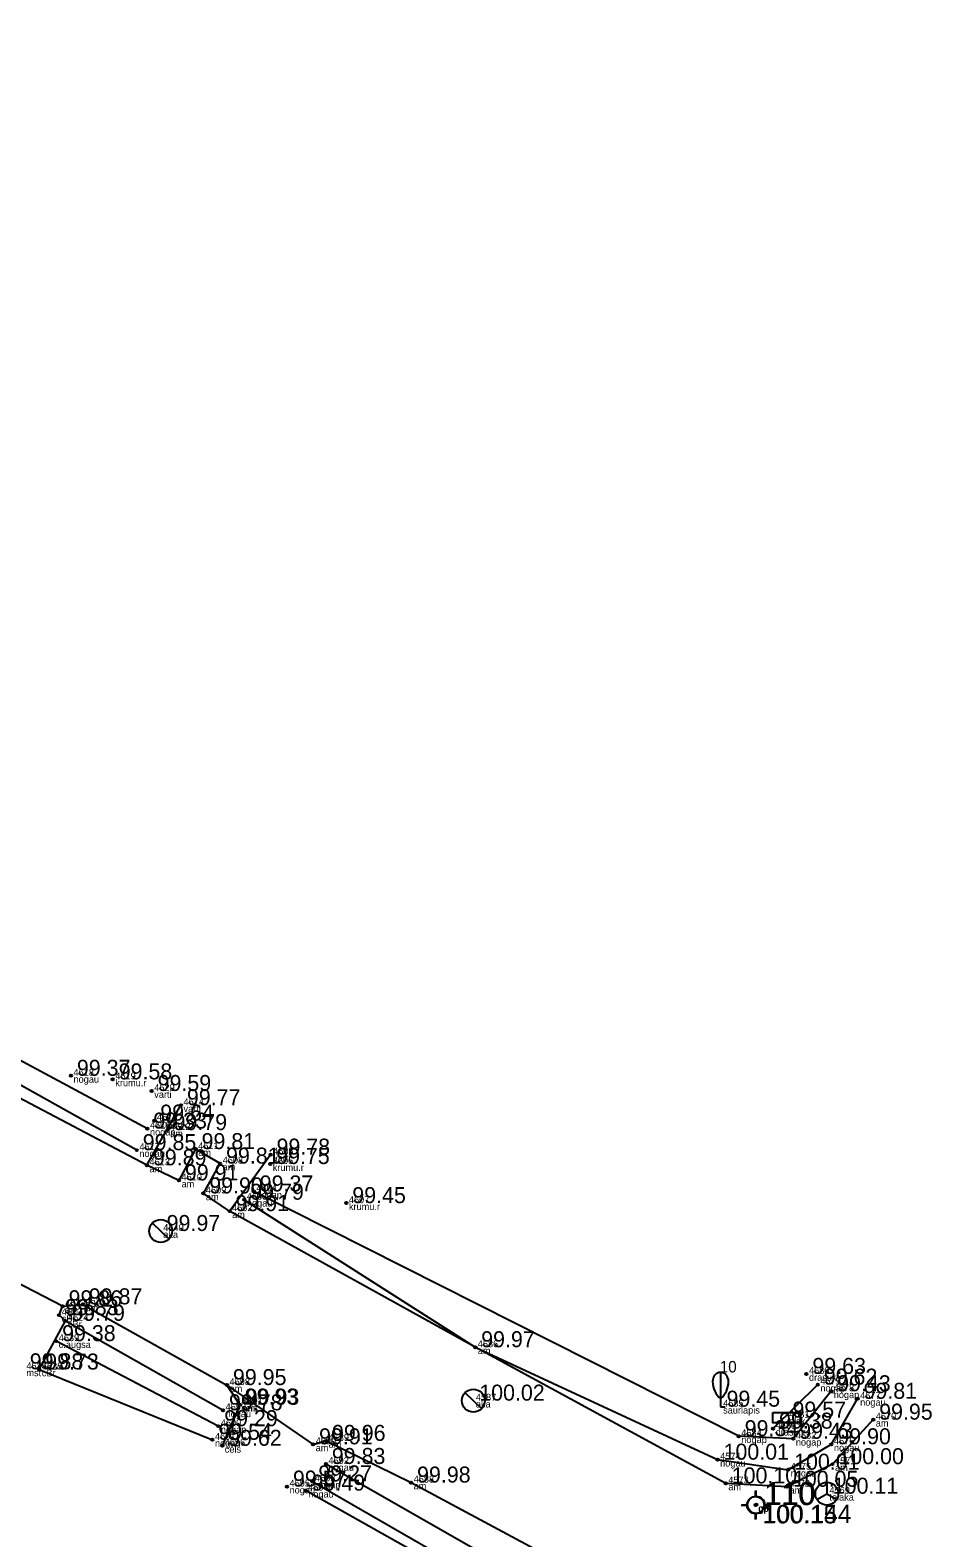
# Model space of a CAD drawing. Extents: x 614911 to 615803, y 262110 to 264311.
# Drawn here: x 615500.1 to 615539.6, y 263975 to 264041 of the extents above; entities that cross this region are included whole.
import ezdxf

# ---------------------------------------------------------------- set-up
doc = ezdxf.new("R2010")
doc.units = 0
for name, color, linetype in [('Level 1', 7, 'Continuous'), ('Level 12', 7, 'Continuous'), ('Level 18', 7, 'Continuous'), ('Level 19', 7, 'Continuous'), ('Level 31', 7, 'Continuous'), ('Level 37', 7, 'Continuous'), ('Level 49', 7, 'Continuous'), ('Level 53', 7, 'Continuous'), ('Level 54', 7, 'Continuous'), ('Level 57', 7, 'Continuous'), ('Level 58', 7, 'Continuous')]:
    doc.layers.add(name, color=color, linetype=linetype)

msp = doc.modelspace()

# ---------------------------------------------------------------- linework, layer by layer
at = {"layer": 'Level 1'}
for p, q in [((615530.34, 263981.133), (615530.34, 263980.781)), ((615530.34, 263980.781), (615530.54, 263980.781))]:
    msp.add_line(p, q, dxfattribs=at)
msp.add_lwpolyline([(615530.34, 263982.281), (615530.34, 263981.133)], dxfattribs=at)
for centre, major_axis, start_param, end_param in [((615530.34, 263981.881), (0, 0.4), 0, 1.570796), ((615530.34, 263981.881), (0, -0.4), 1.570796, 3.141593), ((615530.815, 263981.904), (0, -0.943), 4.7372, 5.669711), ((615529.865, 263981.904), (0, -0.943), 0.613474, 1.545985)]:
    msp.add_ellipse(centre, major_axis=major_axis, ratio=0.875, start_param=start_param, end_param=end_param, dxfattribs=at)
at = {"layer": 'Level 12'}
for p, q in [((615505.488, 263988.819), (615506.206, 263988.123)), ((615519.163, 263981.394), (615519.881, 263980.698))]:
    msp.add_line(p, q, dxfattribs=at)
for centre in [(615505.847, 263988.471), (615519.522, 263981.046)]:
    msp.add_circle(centre, 0.5, dxfattribs=at)
at = {"layer": 'Level 18'}
msp.add_lwpolyline([(615532.625, 263980.528), (615533.825, 263980.528), (615533.825, 263980.078), (615532.625, 263980.078)], close=True, dxfattribs=at)
at = {"layer": 'Level 19'}
for p, q in [((615531.87, 263976.847), (615531.87, 263977.097)), ((615531.898, 263976.862), (615531.898, 263977.112)), ((615531.245, 263976.472), (615531.495, 263976.472)), ((615531.273, 263976.487), (615531.523, 263976.487)), ((615531.87, 263975.847), (615531.87, 263976.097)), ((615531.898, 263975.862), (615531.898, 263976.112)), ((615532.245, 263976.472), (615532.495, 263976.472)), ((615532.273, 263976.487), (615532.523, 263976.487))]:
    msp.add_line(p, q, dxfattribs=at)
for centre, radius in [((615531.87, 263976.472), 0.375), ((615531.898, 263976.487), 0.375), ((615531.87, 263976.472), 0.05), ((615531.898, 263976.487), 0.05)]:
    msp.add_circle(centre, radius, dxfattribs=at)
at = {"layer": 'Level 31'}
for p, q in [((615490.259, 264001.022), (615505.267, 263992.954)), ((615504.802, 263992.01), (615490.144, 264000.195)), ((615501.678, 263984.54), (615508.574, 263980.623)), ((615508.365, 263979.928), (615501.274, 263983.65)), ((615500.537, 263982.407), (615508.11, 263979.333)), ((615534.594, 263981.747), (615532.638, 263979.82)), ((615513.073, 263978.273), (615525.235, 263971.339)), ((615512.485, 263977.512), (615524.919, 263970.351)), ((615525.038, 263969.877), (615512.188, 263977.106))]:
    msp.add_line(p, q, dxfattribs=at)
for points in [[(615509.505, 263989.841), (615519.606, 263983.384), (615530.208, 263978.462), (615533.296, 263978.023), (615535.187, 263979.135), (615536.333, 263981.126)], [(615535.178, 263981.456), (615533.52, 263979.377), (615531.133, 263979.489), (615509.919, 263990.203)]]:
    msp.add_lwpolyline(points, dxfattribs=at)
at = {"layer": 'Level 37'}
msp.add_line((615501.557, 263985.176), (615497.443, 263987.306), dxfattribs=at)
for points in [[(615505.246, 263991.346), (615490.236, 263999.257), (615489.731, 263999.646), (615489.58, 264000.276), (615489.315, 264000.521), (615486.62, 264001.883), (615485.756, 264001.708), (615471.478, 264009.412), (615462.339, 264014.329), (615453.258, 264019.469), (615453.074, 264019.991), (615449.99, 264021.661), (615449.426, 264021.395), (615431.556, 264030.923), (615420.286, 264037.155), (615419.751, 264038.201), (615421.27, 264041.035)], [(615508.86, 263989.34), (615507.712, 263990.116), (615508.446, 263991.422), (615507.375, 263992.055), (615506.646, 263990.685), (615505.246, 263991.346), (615506.733, 263993.979)], [(615537.017, 263980.213), (615535.235, 263978.264), (615533.243, 263977.276), (615530.566, 263977.424), (615519.606, 263983.384), (615508.86, 263989.34), (615510.655, 263991.815)], [(615500.537, 263982.407), (615501.678, 263984.54), (615501.403, 263984.786), (615501.557, 263985.176), (615502.442, 263985.261), (615508.747, 263981.727), (615509.307, 263980.864), (615508.537, 263979.069)], [(615508.747, 263981.727), (615512.515, 263979.133), (615513.08, 263979.284), (615516.802, 263977.461), (615525.807, 263972.632), (615527.94, 263970.217), (615529.065, 263967.543), (615528.62, 263963.507)]]:
    msp.add_lwpolyline(points, dxfattribs=at)
at = {"layer": 'Level 49'}
for p, q in [((615534.988, 263977.472), (615534.988, 263976.972)), ((615534.555, 263976.722), (615534.988, 263976.972)), ((615534.988, 263976.972), (615535.421, 263976.722))]:
    msp.add_line(p, q, dxfattribs=at)
msp.add_circle((615534.988, 263976.972), 0.5, dxfattribs=at)
at = {"layer": 'Level 57'}
for centre in [(615501.921, 263995.265), (615503.75, 263995.108), (615505.452, 263994.6), (615506.733, 263993.979), (615505.57, 263993.302), (615505.267, 263992.954), (615506.148, 263992.887), (615504.802, 263992.01), (615507.375, 263992.055), (615510.655, 263991.815), (615505.246, 263991.346), (615508.446, 263991.422), (615510.637, 263991.403), (615506.646, 263990.685), (615507.712, 263990.116), (615509.505, 263989.841), (615509.919, 263990.203), (615508.86, 263989.34), (615513.969, 263989.691), (615501.557, 263985.176), (615502.442, 263985.261), (615501.403, 263984.786), (615501.678, 263984.54), (615501.274, 263983.65), (615519.606, 263983.384), (615500.537, 263982.407), (615534.096, 263982.215), (615508.747, 263981.727), (615534.594, 263981.747), (615535.178, 263981.456), (615508.574, 263980.623), (615509.265, 263980.876), (615509.307, 263980.864), (615536.333, 263981.126), (615508.365, 263979.928), (615537.017, 263980.213), (615508.11, 263979.333), (615513.08, 263979.284), (615531.133, 263979.489), (615532.638, 263979.82), (615533.52, 263979.377), (615508.537, 263979.069), (615512.515, 263979.133), (615535.187, 263979.135), (615513.073, 263978.273), (615530.208, 263978.462), (615533.296, 263978.023), (615535.235, 263978.264), (615511.372, 263977.284), (615512.485, 263977.512), (615516.802, 263977.461), (615530.566, 263977.424), (615533.243, 263977.276), (615512.188, 263977.106)]:
    msp.add_circle(centre, 0.05, dxfattribs=at)
at = {"layer": 'Level 58'}
for centre in [(615501.921, 263995.265), (615503.75, 263995.108), (615505.452, 263994.6), (615506.733, 263993.979), (615505.57, 263993.302), (615505.267, 263992.954), (615506.148, 263992.887), (615504.802, 263992.01), (615507.375, 263992.055), (615510.655, 263991.815), (615505.246, 263991.346), (615508.446, 263991.422), (615510.637, 263991.403), (615506.646, 263990.685), (615507.712, 263990.116), (615509.505, 263989.841), (615509.919, 263990.203), (615508.86, 263989.34), (615513.969, 263989.691), (615501.557, 263985.176), (615502.442, 263985.261), (615501.403, 263984.786), (615501.678, 263984.54), (615501.274, 263983.65), (615519.606, 263983.384), (615500.537, 263982.407), (615534.096, 263982.215), (615508.747, 263981.727), (615534.594, 263981.747), (615535.178, 263981.456), (615508.574, 263980.623), (615509.265, 263980.876), (615509.307, 263980.864), (615536.333, 263981.126), (615508.365, 263979.928), (615537.017, 263980.213), (615508.11, 263979.333), (615513.08, 263979.284), (615531.133, 263979.489), (615532.638, 263979.82), (615533.52, 263979.377), (615508.537, 263979.069), (615512.515, 263979.133), (615535.187, 263979.135), (615513.073, 263978.273), (615530.208, 263978.462), (615533.296, 263978.023), (615535.235, 263978.264), (615511.372, 263977.284), (615512.485, 263977.512), (615516.802, 263977.461), (615530.566, 263977.424), (615533.243, 263977.276), (615512.188, 263977.106)]:
    msp.add_circle(centre, 0.05, dxfattribs=at)

# ---------------------------------------------------------------- texts
at = {"layer": 'Level 1'}
msp.add_text(' 10', height=0.5, dxfattribs=at).set_placement((615530.115, 263982.281))
at = {"layer": 'Level 19'}
for s, height, p in [(' 110', 1, (615531.87, 263976.472)), (' 110', 1, (615531.898, 263976.487)), (' 100.15', 0.8, (615531.87, 263975.672)), (' 100.144', 0.8, (615531.898, 263975.687))]:
    msp.add_text(s, height=height, dxfattribs=at).set_placement(p)
at = {"layer": 'Level 49'}
msp.add_text(' 100.11', height=0.7, dxfattribs=at).set_placement((615534.988, 263976.972))
at = {"layer": 'Level 53'}
for s, p in [(' nogau', (615501.921, 263994.965)), (' krumu.r', (615503.75, 263994.808)), (' varti', (615505.452, 263994.3)), (' varti', (615506.733, 263993.679)), (' nogau', (615505.57, 263993.002)), (' nogap', (615505.267, 263992.654)), (' am', (615506.148, 263992.587)), (' nogau', (615504.802, 263991.71)), (' am', (615507.375, 263991.755)), (' varti', (615510.655, 263991.515)), (' am', (615505.246, 263991.046)), (' am', (615508.446, 263991.122)), (' krumu.r', (615510.637, 263991.103)), (' am', (615506.646, 263990.385)), (' am', (615507.712, 263989.816)), (' nogap', (615509.919, 263989.903)), (' am', (615508.86, 263989.04)), (' nogau', (615509.505, 263989.541)), (' krumu.r', (615513.969, 263989.391)), (' aka', (615505.847, 263988.171)), (' cBr', (615501.403, 263984.486)), (' am', (615501.557, 263984.876)), (' am', (615502.442, 263984.961)), (' cBr', (615501.678, 263984.24)), (' c.augsa', (615501.274, 263983.35)), (' am', (615519.606, 263983.084)), (' mst', (615499.86, 263982.117)), (' cBr', (615500.537, 263982.107)), (' drasu.z', (615534.096, 263981.915)), (' am', (615508.747, 263981.427)), (' nogap', (615534.594, 263981.447)), (' nogap', (615535.178, 263981.156)), (' cels', (615509.265, 263980.576)), (' am', (615509.307, 263980.564)), (' aka', (615519.522, 263980.746)), (' saurlapis', (615530.34, 263980.481)), (' nogau', (615536.333, 263980.826)), (' nogau', (615508.574, 263980.323)), (' elsk', (615533.225, 263980.003)), (' am', (615537.017, 263979.913)), (' nogap', (615508.365, 263979.628)), (' nogap', (615531.133, 263979.189)), (' drasu.z', (615532.638, 263979.52)), (' nogap', (615533.52, 263979.077)), (' nogau', (615508.11, 263979.033)), (' cels', (615508.537, 263978.769)), (' am', (615512.515, 263978.833)), (' am', (615513.08, 263978.984)), (' nogau', (615535.187, 263978.835)), (' nogau', (615513.073, 263977.973)), (' nogau', (615530.208, 263978.162)), (' nogau', (615533.296, 263977.723)), (' am', (615535.235, 263977.964)), (' nogap', (615512.485, 263977.212)), (' am', (615516.802, 263977.161)), (' am', (615530.566, 263977.124)), (' nogau', (615511.372, 263976.984)), (' nogau', (615512.188, 263976.806)), (' am', (615533.243, 263976.976)), (' telaka', (615534.988, 263976.672)), (' gp', (615531.87, 263976.172)), (' gp', (615531.898, 263976.187))]:
    msp.add_text(s, height=0.3, dxfattribs=at).set_placement(p)
at = {"layer": 'Level 54'}
for s, p in [(' 4618', (615501.921, 263995.265)), (' 4619', (615503.75, 263995.108)), (' 4620', (615505.452, 263994.6)), (' 4614', (615506.733, 263993.979)), (' 4616', (615505.267, 263992.954)), (' 4615', (615505.57, 263993.302)), (' 4612', (615506.148, 263992.887)), (' 4617', (615504.802, 263992.01)), (' 4611', (615507.375, 263992.055)), (' 4605', (615510.655, 263991.815)), (' 4613', (615505.246, 263991.346)), (' 4608', (615508.446, 263991.422)), (' 4606', (615510.637, 263991.403)), (' 4610', (615506.646, 263990.685)), (' 4604', (615509.919, 263990.203)), (' 4609', (615507.712, 263990.116)), (' 4603', (615509.505, 263989.841)), (' 4607', (615513.969, 263989.691)), (' 4602', (615508.86, 263989.34)), (' 4640', (615505.847, 263988.471)), (' 4622', (615501.557, 263985.176)), (' 4621', (615502.442, 263985.261)), (' 4623', (615501.403, 263984.786)), (' 4624', (615501.678, 263984.54)), (' 4639', (615501.274, 263983.65)), (' 4586', (615519.606, 263983.384)), (' 4626', (615499.86, 263982.417)), (' 4625', (615500.537, 263982.407)), (' 4598', (615508.747, 263981.727)), (' 4580', (615534.096, 263982.215)), (' 4579', (615534.594, 263981.747)), (' 4587', (615519.522, 263981.046)), (' 4578', (615535.178, 263981.456)), (' 4577', (615536.333, 263981.126)), (' 4599', (615508.574, 263980.623)), (' 4597', (615509.265, 263980.876)), (' 4591', (615509.307, 263980.864)), (' 4585', (615530.34, 263980.781)), (' 4581', (615533.225, 263980.303)), (' 4600', (615508.365, 263979.928)), (' 4583', (615532.638, 263979.82)), (' 4570', (615537.017, 263980.213)), (' 4601', (615508.11, 263979.333)), (' 4596', (615508.537, 263979.069)), (' 4590', (615512.515, 263979.133)), (' 4589', (615513.08, 263979.284)), (' 4584', (615531.133, 263979.489)), (' 4582', (615533.52, 263979.377)), (' 4576', (615535.187, 263979.135)), (' 4574', (615530.208, 263978.462)), (' 4592', (615513.073, 263978.273)), (' 4575', (615533.296, 263978.023)), (' 4571', (615535.235, 263978.264)), (' 4595', (615511.372, 263977.284)), (' 4594', (615512.188, 263977.106)), (' 4593', (615512.485, 263977.512)), (' 4588', (615516.802, 263977.461)), (' 4573', (615530.566, 263977.424)), (' 4572', (615533.243, 263977.276)), (' 4569', (615534.988, 263976.972))]:
    msp.add_text(s, height=0.3, dxfattribs=at).set_placement(p)
at = {"layer": 'Level 58'}
for s, p in [(' 99.37', (615501.921, 263995.265)), (' 99.58', (615503.75, 263995.108)), (' 99.59', (615505.452, 263994.6)), (' 99.77', (615506.733, 263993.979)), (' 99.64', (615505.57, 263993.302)), (' 99.33', (615505.267, 263992.954)), (' 99.79', (615506.148, 263992.887)), (' 99.85', (615504.802, 263992.01)), (' 99.81', (615507.375, 263992.055)), (' 99.78', (615510.655, 263991.815)), (' 99.89', (615505.246, 263991.346)), (' 99.81', (615508.446, 263991.422)), (' 99.75', (615510.637, 263991.403)), (' 99.91', (615506.646, 263990.685)), (' 99.90', (615507.712, 263990.116)), (' 99.79', (615509.505, 263989.841)), (' 99.37', (615509.919, 263990.203)), (' 99.91', (615508.86, 263989.34)), (' 99.45', (615513.969, 263989.691)), (' 99.97', (615505.847, 263988.471)), (' 99.86', (615501.557, 263985.176)), (' 99.87', (615502.442, 263985.261)), (' 99.83', (615501.403, 263984.786)), (' 99.79', (615501.678, 263984.54)), (' 99.38', (615501.274, 263983.65)), (' 99.97', (615519.606, 263983.384)), (' 99.88', (615499.86, 263982.417)), (' 99.73', (615500.537, 263982.407)), (' 99.63', (615534.096, 263982.215)), (' 99.95', (615508.747, 263981.727)), (' 99.62', (615534.594, 263981.747)), (' 99.43', (615535.178, 263981.456)), (' 99.78', (615508.574, 263980.623)), (' 99.93', (615509.265, 263980.876)), (' 99.93', (615509.307, 263980.864)), (' 100.02', (615519.522, 263981.046)), (' 99.45', (615530.34, 263980.781)), (' 99.81', (615536.333, 263981.126)), (' 99.29', (615508.365, 263979.928)), (' 99.57', (615533.225, 263980.303)), (' 99.95', (615537.017, 263980.213)), (' 99.54', (615508.11, 263979.333)), (' 99.96', (615513.08, 263979.284)), (' 99.34', (615531.133, 263979.489)), (' 99.38', (615532.638, 263979.82)), (' 99.43', (615533.52, 263979.377)), (' 99.62', (615508.537, 263979.069)), (' 99.91', (615512.515, 263979.133)), (' 99.90', (615535.187, 263979.135)), (' 99.83', (615513.073, 263978.273)), (' 100.01', (615530.208, 263978.462)), (' 100.01', (615533.296, 263978.023)), (' 100.00', (615535.235, 263978.264)), (' 99.57', (615511.372, 263977.284)), (' 99.27', (615512.485, 263977.512)), (' 99.98', (615516.802, 263977.461)), (' 100.10', (615530.566, 263977.424)), (' 100.05', (615533.243, 263977.276)), (' 99.49', (615512.188, 263977.106))]:
    msp.add_text(s, height=0.7, dxfattribs=at).set_placement(p)

doc.saveas('drawing.dxf')
